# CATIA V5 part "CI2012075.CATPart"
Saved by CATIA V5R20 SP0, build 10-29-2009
Part number: CI2012075
Bounding box of the stored display mesh (mm): x -12 to 12, y -9.679 to 93, z -16.11 to 13.284
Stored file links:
  C:\Users\Raffaele\Desktop\3D X SITO CF\BOLEX\19-INCLINED ASSEMBLY REF_CI\CI2012075.CATPart

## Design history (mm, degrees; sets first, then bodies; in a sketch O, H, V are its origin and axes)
Set1
  DatumSurface1 to DatumSurface16 "MANIFOLD_SOLID_BREP #379"
  DatumSurface17 to DatumSurface39 "MANIFOLD_SOLID_BREP #1098"
Body1 (main body)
